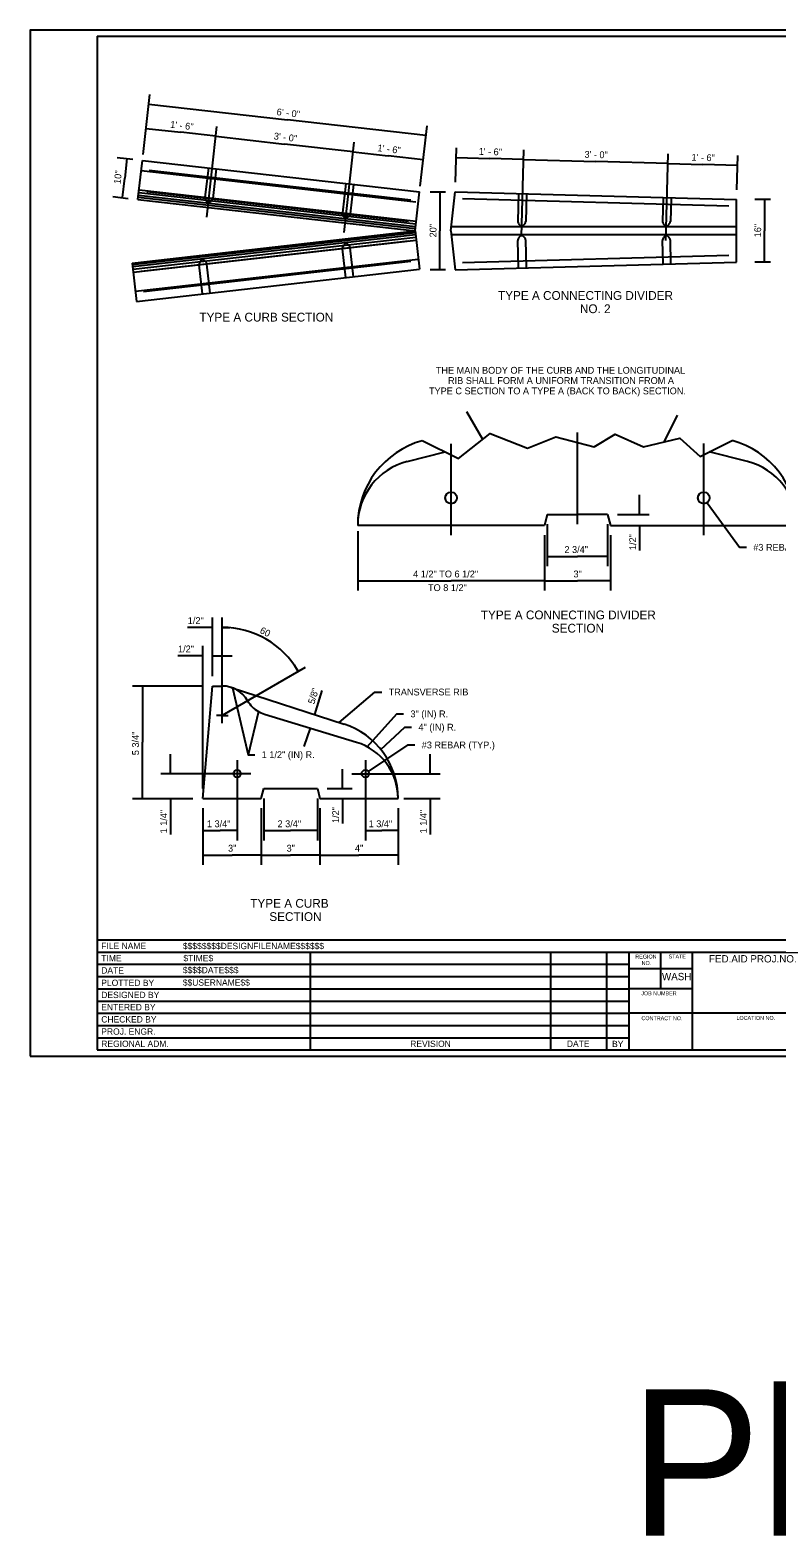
# Model space of a CAD drawing. Extents: x 99988 to 100172, y 99995 to 100047.
# Drawn here: x 99999.31 to 100006.96, y 99995.01 to 100010.44 of the extents above; entities that cross this region are included whole.
import ezdxf

# ---------------------------------------------------------------- set-up
doc = ezdxf.new("R2010")
doc.units = 0
for name, color, linetype in [('Level 1', 7, 'Continuous'), ('Level 15', 7, 'Continuous'), ('Level 2', 7, 'Continuous'), ('Level 20', 7, 'Continuous'), ('Level 27', 7, 'Continuous'), ('SH_GI_PlotLimits', 7, 'Continuous'), ('SH_GI_SheetBorder', 7, 'Continuous'), ('SH_GI_SheetLocationText', 7, 'Continuous'), ('SH_GI_SheetTextInCells', 7, 'Continuous'), ('SH_GI_TitleBlockText', 7, 'Continuous'), ('SH_RS_ConstructionNoteFlag', 7, 'Continuous'), ('SH_RS_DimensionLines', 7, 'Continuous')]:
    doc.layers.add(name, color=color, linetype=linetype)

msp = doc.modelspace()

# ---------------------------------------------------------------- linework, layer by layer
at = {"layer": 'Level 1'}
for centre, radius in [((100003.624, 100005.65), 0.06), ((100006.211, 100005.65), 0.06), ((100001.433, 100002.827), 0.0379), ((100002.746, 100002.827), 0.0379)]:
    msp.add_circle(centre, radius, dxfattribs=at)
at = {"layer": 'Level 15'}
for p, q in [((100000.469, 100009.164), (100000.539, 100009.78)), ((100000.528, 100009.681), (100001.947, 100009.52)), ((100000.5, 100009.432), (100000.857, 100009.392)), ((100001.214, 100009.351), (100000.857, 100009.392)), ((100001.121, 100008.524), (100001.226, 100009.451)), ((100003.366, 100009.359), (100001.947, 100009.52)), ((100003.308, 100008.842), (100003.377, 100009.458)), ((100001.214, 100009.351), (100001.918, 100009.272)), ((100002.621, 100009.192), (100001.918, 100009.272)), ((100002.527, 100008.365), (100002.632, 100009.291)), ((100003.67, 100008.883), (100003.68, 100009.233)), ((100004.344, 100008.324), (100004.368, 100009.214)), ((100000.204, 100009.134), (100000.363, 100009.116)), ((100000.303, 100009.123), (100000.281, 100008.923)), ((100002.621, 100009.192), (100002.978, 100009.151)), ((100003.336, 100009.111), (100002.978, 100009.151)), ((100003.677, 100009.133), (100004.021, 100009.124)), ((100004.366, 100009.114), (100004.021, 100009.124)), ((100004.366, 100009.114), (100005.105, 100009.094)), ((100005.845, 100009.073), (100005.105, 100009.094)), ((100005.823, 100008.283), (100005.848, 100009.173)), ((100005.845, 100009.073), (100006.201, 100009.063)), ((100006.557, 100009.053), (100006.201, 100009.063)), ((100006.55, 100008.803), (100006.56, 100009.153)), ((100000.258, 100008.723), (100000.281, 100008.923)), ((100003.409, 100008.783), (100003.566, 100008.783)), ((100003.509, 100008.783), (100003.509, 100008.383)), ((100000.159, 100008.734), (100000.318, 100008.716)), ((100006.894, 100008.704), (100006.734, 100008.704)), ((100006.834, 100008.704), (100006.834, 100008.384)), ((100003.509, 100007.984), (100003.509, 100008.383)), ((100006.834, 100008.064), (100006.834, 100008.384)), ((100003.566, 100007.984), (100003.409, 100007.984)), ((100006.894, 100008.064), (100006.734, 100008.064)), ((100003.948, 100006.249), (100003.785, 100006.53)), ((100005.805, 100006.222), (100005.942, 100006.498)), ((100004.917, 100005.381), (100004.917, 100006.32)), ((100003.624, 100005.268), (100003.624, 100006.202)), ((100006.211, 100005.268), (100006.211, 100006.205)), ((100004.608, 100005.381), (100004.608, 100004.951)), ((100005.227, 100005.381), (100005.227, 100004.951)), ((100005.327, 100005.481), (100005.653, 100005.481)), ((100002.667, 100005.308), (100002.667, 100004.701)), ((100004.58, 100005.268), (100004.58, 100004.701)), ((100005.255, 100005.268), (100005.255, 100004.701)), ((100004.608, 100005.051), (100004.917, 100005.051)), ((100005.227, 100005.051), (100004.917, 100005.051)), ((100002.667, 100004.801), (100003.624, 100004.801)), ((100004.58, 100004.801), (100003.624, 100004.801)), ((100004.58, 100004.801), (100004.917, 100004.801)), ((100005.255, 100004.801), (100004.917, 100004.801)), ((100001.18, 100003.824), (100001.18, 100004.424)), ((100001.28, 100003.344), (100001.28, 100004.424)), ((100001.08, 100002.674), (100001.08, 100004.134)), ((100002.129, 100003.914), (100001.28, 100003.424)), ((100001.08, 100003.724), (100000.362, 100003.724)), ((100000.462, 100003.724), (100000.462, 100003.149)), ((100001.28, 100003.424), (100001.22, 100003.424)), ((100001.28, 100003.424), (100001.34, 100003.424)), ((100000.462, 100002.574), (100000.462, 100003.149)), ((100000.75, 100002.827), (100000.75, 100003.027)), ((100003.41, 100002.827), (100003.41, 100003.027)), ((100002.355, 100002.674), (100002.611, 100002.674)), ((100000.362, 100002.574), (100000.98, 100002.574)), ((100001.08, 100002.474), (100001.08, 100001.894)), ((100001.68, 100002.474), (100001.68, 100001.894)), ((100001.705, 100002.574), (100001.705, 100002.144)), ((100002.255, 100002.574), (100002.255, 100002.144)), ((100002.28, 100002.474), (100002.28, 100001.894)), ((100003.08, 100002.474), (100003.08, 100001.894)), ((100003.14, 100002.574), (100003.51, 100002.574)), ((100001.08, 100002.244), (100001.257, 100002.244)), ((100001.433, 100002.244), (100001.257, 100002.244)), ((100001.705, 100002.244), (100001.98, 100002.244)), ((100002.255, 100002.244), (100001.98, 100002.244)), ((100002.746, 100002.244), (100002.913, 100002.244)), ((100003.08, 100002.244), (100002.913, 100002.244)), ((100001.08, 100001.994), (100001.38, 100001.994)), ((100001.68, 100001.994), (100001.38, 100001.994)), ((100001.68, 100001.994), (100001.98, 100001.994)), ((100002.28, 100001.994), (100001.98, 100001.994)), ((100002.28, 100001.994), (100002.68, 100001.994)), ((100003.08, 100001.994), (100002.68, 100001.994))]:
    msp.add_line(p, q, dxfattribs=at)
for points in [[(100006.246, 100005.601), (100006.578, 100005.144), (100006.648, 100005.144)], [(100001.28, 100004.324), (100001.355, 100004.321)], [(100002.059, 100003.874), (100002.019, 100003.937)], [(100001.386, 100003.705), (100001.544, 100003.021)], [(100002.476, 100003.352), (100002.844, 100003.663), (100002.914, 100003.663)], [(100001.65, 100003.464), (100001.544, 100003.021), (100001.614, 100003.021)], [(100002.763, 100003.103), (100003.067, 100003.439), (100003.137, 100003.439)], [(100002.903, 100003.076), (100003.149, 100003.303), (100003.219, 100003.303)], [(100002.777, 100002.848), (100003.183, 100003.121), (100003.253, 100003.121)]]:
    msp.add_lwpolyline(points, dxfattribs=at)
msp.add_arc((100001.28, 100003.424), 0.9, 30.0003, 90, dxfattribs=at)
at = {"layer": 'Level 2'}
for p, q in [((100000.417, 100008.705), (100000.462, 100009.105)), ((100000.462, 100009.105), (100003.301, 100008.783)), ((100000.531, 100009.004), (100003.211, 100008.7)), ((100001.138, 100009.028), (100001.103, 100008.724)), ((100001.218, 100009.019), (100001.183, 100008.715)), ((100000.507, 100008.787), (100003.186, 100008.484)), ((100002.544, 100008.868), (100002.51, 100008.566)), ((100002.625, 100008.859), (100002.59, 100008.556)), ((100003.255, 100008.383), (100003.301, 100008.783)), ((100003.622, 100008.384), (100003.667, 100008.784)), ((100003.667, 100008.784), (100006.547, 100008.704)), ((100004.315, 100008.767), (100004.308, 100008.482)), ((100004.396, 100008.762), (100004.388, 100008.48)), ((100000.417, 100008.705), (100003.255, 100008.383)), ((100003.257, 100008.404), (100000.419, 100008.724)), ((100001.136, 100008.663), (100001.111, 100008.695)), ((100001.136, 100008.663), (100001.168, 100008.688)), ((100006.467, 100008.635), (100003.739, 100008.711)), ((100005.795, 100008.726), (100005.788, 100008.482)), ((100005.876, 100008.721), (100005.869, 100008.48)), ((100006.547, 100008.064), (100006.547, 100008.704)), ((100002.543, 100008.504), (100002.518, 100008.536)), ((100002.543, 100008.504), (100002.575, 100008.53)), ((100004.346, 100008.424), (100004.318, 100008.453)), ((100004.346, 100008.424), (100004.376, 100008.452)), ((100005.827, 100008.424), (100005.799, 100008.453)), ((100005.827, 100008.424), (100005.857, 100008.452)), ((100000.359, 100008.054), (100003.255, 100008.383)), ((100003.258, 100008.362), (100000.361, 100008.035)), ((100003.255, 100008.383), (100003.3, 100007.99)), ((100003.622, 100008.384), (100003.667, 100007.984)), ((100004.346, 100008.343), (100004.318, 100008.314)), ((100004.346, 100008.343), (100004.376, 100008.315)), ((100005.827, 100008.343), (100005.799, 100008.314)), ((100005.827, 100008.343), (100005.856, 100008.315)), ((100000.449, 100007.971), (100003.186, 100008.282)), ((100002.544, 100007.904), (100002.51, 100008.2)), ((100002.544, 100008.261), (100002.519, 100008.229)), ((100002.544, 100008.261), (100002.575, 100008.236)), ((100002.624, 100007.913), (100002.59, 100008.209)), ((100004.315, 100008), (100004.307, 100008.285)), ((100004.396, 100008.005), (100004.388, 100008.287)), ((100005.795, 100008.041), (100005.788, 100008.285)), ((100005.875, 100008.046), (100005.869, 100008.287)), ((100000.359, 100008.054), (100000.403, 100007.661)), ((100000.403, 100007.661), (100003.3, 100007.99)), ((100000.472, 100007.762), (100003.21, 100008.073)), ((100001.076, 100007.738), (100001.042, 100008.034)), ((100001.075, 100008.095), (100001.05, 100008.064)), ((100001.075, 100008.095), (100001.107, 100008.07)), ((100001.156, 100007.747), (100001.122, 100008.043)), ((100003.667, 100007.984), (100006.547, 100008.064)), ((100006.467, 100008.131), (100003.739, 100008.055)), ((100003.175, 100006.022), (100003.564, 100006.121)), ((100003.175, 100006.022), (100003.175, 100006.022)), ((100006.66, 100006.022), (100006.268, 100006.121)), ((100006.66, 100006.022), (100006.66, 100006.022)), ((100004.58, 100005.368), (100002.667, 100005.368)), ((100004.608, 100005.481), (100004.58, 100005.368)), ((100004.608, 100005.481), (100004.917, 100005.481)), ((100005.227, 100005.481), (100004.917, 100005.481)), ((100005.227, 100005.481), (100005.255, 100005.368)), ((100005.255, 100005.368), (100007.167, 100005.368)), ((100001.08, 100002.574), (100001.18, 100003.724)), ((100001.18, 100003.724), (100001.28, 100003.724)), ((100001.372, 100003.71), (100002.527, 100003.335)), ((100001.711, 100003.437), (100002.656, 100003.148)), ((100001.433, 100002.964), (100001.433, 100002.144)), ((100002.746, 100002.964), (100002.746, 100002.144)), ((100001.571, 100002.827), (100000.65, 100002.827)), ((100002.608, 100002.827), (100003.51, 100002.827)), ((100001.68, 100002.574), (100001.705, 100002.674)), ((100001.705, 100002.674), (100002.255, 100002.674)), ((100002.255, 100002.674), (100002.28, 100002.574)), ((100001.08, 100002.574), (100001.68, 100002.574)), ((100002.28, 100002.574), (100003.08, 100002.574))]:
    msp.add_line(p, q, dxfattribs=at)
msp.add_lwpolyline([(100003.328, 100006.236), (100003.7, 100006.054), (100004.025, 100006.31), (100004.405, 100006.158), (100004.695, 100006.275), (100005.089, 100006.171), (100005.303, 100006.303), (100005.593, 100006.171), (100005.967, 100006.261), (100006.174, 100006.075), (100006.503, 100006.237)], dxfattribs=at)
for centre, radius, start, end in [((100001.142, 100008.72), 0.04, 173.435, 218.435), ((100001.143, 100008.72), 0.04, 308.435, 353.435), ((100002.549, 100008.561), 0.04, 173.435, 218.435), ((100002.55, 100008.561), 0.04, 308.435, 353.435), ((100004.348, 100008.481), 0.04, 178.4171, 223.4171), ((100004.348, 100008.481), 0.04, 313.4171, 358.4171), ((100005.828, 100008.481), 0.04, 178.4298, 223.4298), ((100005.829, 100008.481), 0.04, 313.4298, 358.4298), ((100004.347, 100008.286), 0.04, 136.5372, 181.5372), ((100004.348, 100008.286), 0.04, 1.5372, 46.5372), ((100005.828, 100008.286), 0.04, 136.5467, 181.5467), ((100005.829, 100008.286), 0.04, 1.5467, 46.5467), ((100002.55, 100008.204), 0.04, 141.5636, 186.5636), ((100002.551, 100008.205), 0.04, 6.5636, 51.5636), ((100001.082, 100008.039), 0.04, 141.5636, 186.5636), ((100001.082, 100008.039), 0.04, 6.5636, 51.5636), ((100003.567, 100005.368), 0.9, 105.4337, 180), ((100006.267, 100005.368), 0.9, 0, 74.8377), ((100003.342, 100005.368), 0.675, 104.338, 180), ((100006.492, 100005.368), 0.675, 0, 75.662), ((100001.28, 100003.424), 0.3, 30, 90), ((100001.799, 100003.724), 0.3, 210, 240.2155), ((100001.799, 100003.724), 0.3, 240.2155, 252.9521), ((100002.28, 100002.574), 0.8, 0, 72.0292), ((100002.48, 100002.574), 0.6, 0, 72.9521)]:
    msp.add_arc(centre, radius, start, end, dxfattribs=at)
at = {"layer": 'Level 27'}
for p, q in [((100000.451, 100009), (100003.263, 100008.681)), ((100003.262, 100008.452), (100000.425, 100008.772)), ((100003.265, 100008.48), (100000.428, 100008.801)), ((100003.259, 100008.424), (100000.421, 100008.744)), ((100003.26, 100008.342), (100000.363, 100008.015)), ((100003.263, 100008.314), (100000.366, 100007.987)), ((100006.547, 100008.424), (100003.626, 100008.424)), ((100006.547, 100008.343), (100003.626, 100008.343)), ((100003.266, 100008.285), (100000.37, 100007.958)), ((100000.391, 100007.766), (100003.288, 100008.094))]:
    msp.add_line(p, q, dxfattribs=at)
at = {"layer": 'SH_GI_PlotLimits'}
msp.add_lwpolyline([(99999.312, 99999.937), (100015.812, 99999.937), (100015.812, 100010.437), (99999.312, 100010.437)], close=True, dxfattribs=at)
at = {"layer": 'SH_GI_SheetBorder'}
for p, q in [((100000, 100010.375), (100000, 100000)), ((100000, 100010.375), (100015.75, 100010.375)), ((100000, 100001.126), (100015.75, 100001.126)), ((100000, 100001.001), (100007.457, 100001.001)), ((100002.179, 100001.001), (100002.179, 100000)), ((100004.641, 100001.001), (100004.641, 100000)), ((100005.216, 100001.001), (100005.216, 100000)), ((100005.445, 100001.001), (100005.445, 100000)), ((100005.772, 100000.625), (100005.772, 100001.001)), ((100006.096, 100000), (100006.096, 100001.001)), ((100000, 100000.876), (100002.182, 100000.876)), ((100000, 100000.751), (100002.182, 100000.751)), ((100002.182, 100000.876), (100005.447, 100000.876)), ((100002.182, 100000.751), (100005.447, 100000.751)), ((100006.096, 100000.831), (100005.447, 100000.831)), ((100000, 100000.625), (100005.447, 100000.625)), ((100006.096, 100000.625), (100005.447, 100000.625)), ((100000, 100000.5), (100005.447, 100000.5)), ((100000, 100000.375), (100005.447, 100000.375)), ((100007.457, 100000.375), (100005.447, 100000.375)), ((100000, 100000.25), (100005.447, 100000.25)), ((100000, 100000.125), (100005.447, 100000.125)), ((100000, 100000), (100015.75, 100000))]:
    msp.add_line(p, q, dxfattribs=at)
at = {"layer": 'SH_RS_DimensionLines'}
for p, q in [((100005.553, 100005.481), (100005.553, 100005.681)), ((100005.553, 100005.368), (100005.553, 100005.112)), ((100001.18, 100004.324), (100000.924, 100004.324)), ((100001.08, 100004.034), (100000.824, 100004.034)), ((100001.18, 100004.034), (100001.38, 100004.034)), ((100002.227, 100003.432), (100002.304, 100003.677)), ((100002.227, 100003.432), (100002.287, 100003.623)), ((100002.181, 100003.293), (100002.117, 100003.104)), ((100002.511, 100002.674), (100002.511, 100002.874)), ((100000.75, 100002.574), (100000.75, 100002.206)), ((100002.511, 100002.574), (100002.511, 100002.318)), ((100003.41, 100002.574), (100003.41, 100002.206))]:
    msp.add_line(p, q, dxfattribs=at)

# ---------------------------------------------------------------- texts
at = {"layer": 'Level 20'}
for s, rotation, p in [('6\' - 0"', 353.5303, (100001.834, 100009.568)), ('1\' - 6"', 353.5303, (100000.744, 100009.44)), ('3\' - 0"', 353.5303, (100001.805, 100009.32)), ('1\' - 6"', 353.5303, (100002.866, 100009.199)), ('1\' - 6"', 358.4089, (100003.905, 100009.162)), ('3\' - 0"', 358.4089, (100004.989, 100009.132)), ('1\' - 6"', 358.4089, (100006.085, 100009.102)), ('10"', 83.5303, (100000.238, 100008.86)), ('20"', 90, (100003.474, 100008.316)), ('16"', 90, (100006.799, 100008.317)), ('THE MAIN BODY OF THE CURB AND THE LONGITUDINAL ', 360, (100003.467, 100006.921)), ('TYPE C SECTION TO A TYPE A (BACK TO BACK) SECTION.', 360, (100003.397, 100006.71)), ('RIB SHALL FORM A UNIFORM TRANSITION FROM A', 360, (100003.592, 100006.816)), ('#3 REBAR (TYP.)', 360, (100006.718, 100005.109)), ('60', 332.6326, (100001.658, 100004.271)), ('TRANSVERSE RIB', 360, (100002.984, 100003.628)), ('3" (IN) R.', 360, (100003.207, 100003.404)), ('5 3/4"', 90, (100000.427, 100003.016)), ('4" (IN) R.', 360, (100003.289, 100003.268)), ('1 1/2" (IN) R.', 360, (100001.684, 100002.986)), ('#3 REBAR (TYP.)', 360, (100003.323, 100003.086)), ('1 3/4"', 360, (100002.779, 100002.279)), ('3"', 360, (100001.339, 100002.029)), ('3"', 360, (100001.939, 100002.029))]:
    msp.add_text(s, height=0.07, rotation=rotation, dxfattribs=at).set_placement(p)
for s, height, p in [('TYPE A CONNECTING DIVIDER', 0.09, (100004.104, 100007.677)), ('TYPE A CURB SECTION', 0.09, (100001.046, 100007.455)), ('NO. 2', 0.09, (100004.943, 100007.541)), ('2 3/4"', 0.07, (100004.784, 100005.086)), ('4 1/2" TO 6 1/2"', 0.07, (100003.235, 100004.836)), ('3"', 0.07, (100004.877, 100004.836)), ('TO 8 1/2"', 0.07, (100003.387, 100004.696)), ('TYPE A CONNECTING DIVIDER', 0.09, (100003.928, 100004.407)), ('SECTION', 0.09, (100004.655, 100004.271)), ('1 3/4"', 0.07, (100001.123, 100002.279)), ('2 3/4"', 0.07, (100001.846, 100002.279)), ('4"', 0.07, (100002.639, 100002.029)), ('TYPE A CURB', 0.09, (100001.567, 100001.455)), ('SECTION', 0.09, (100001.762, 100001.319))]:
    msp.add_text(s, height=height, dxfattribs=at).set_placement(p)
at = {"layer": 'SH_GI_SheetLocationText'}
msp.add_text('Plot 1', height=1.5, dxfattribs=at).set_placement((100005.455, 99995.027))
at = {"layer": 'SH_GI_SheetTextInCells'}
for s, height, p in [('FILE NAME', 0.0651, (100000.041, 100001.031)), ('TIME', 0.0651, (100000.041, 100000.906)), ('REGION', 0.04, (100005.51, 100000.935)), ('NO.', 0.04, (100005.575, 100000.869)), ('STATE', 0.04, (100005.851, 100000.936)), ('FED.AID PROJ.NO.', 0.07506, (100006.265, 100000.895)), ('DATE', 0.0651, (100000.041, 100000.781)), ('WASH', 0.0751, (100005.783, 100000.713)), ('PLOTTED BY', 0.0651, (100000.041, 100000.654)), ('DESIGNED BY', 0.06505, (100000.041, 100000.53)), ('JOB NUMBER', 0.04, (100005.571, 100000.559)), ('ENTERED BY', 0.0651, (100000.041, 100000.405)), ('CHECKED BY', 0.0651, (100000.041, 100000.28)), ('CONTRACT NO.', 0.04003, (100005.573, 100000.304)), ('LOCATION NO.', 0.04003, (100006.546, 100000.307)), ('PROJ. ENGR.', 0.06505, (100000.041, 100000.155)), ('REGIONAL ADM.', 0.06505, (100000.041, 100000.03)), ('REVISION', 0.0651, (100003.205, 100000.03)), ('DATE', 0.0651, (100004.809, 100000.03)), ('BY', 0.0651, (100005.272, 100000.028))]:
    msp.add_text(s, height=height, dxfattribs=at).set_placement(p)
at = {"layer": 'SH_GI_TitleBlockText'}
for s, height, p in [('$$$$$$$$DESIGNFILENAME$$$$$$', 0.06505, (100000.877, 100001.031)), ('$TIME$', 0.0651, (100000.882, 100000.906)), ('$$$$DATE$$$', 0.06505, (100000.876, 100000.784)), ('$$USERNAME$$', 0.06505, (100000.876, 100000.657))]:
    msp.add_text(s, height=height, dxfattribs=at).set_placement(p)
at = {"layer": 'SH_RS_ConstructionNoteFlag'}
for s, rotation, p in [('1/2"', 90, (100005.518, 100005.116)), ('1/2"', 360, (100000.927, 100004.359)), ('1/2"', 360, (100000.827, 100004.069)), ('5/8"', 72.608, (100002.222, 100003.533)), ('1 1/4"', 90, (100000.715, 100002.216)), ('1/2"', 90, (100002.476, 100002.322)), ('1 1/4"', 90, (100003.375, 100002.216))]:
    msp.add_text(s, height=0.07, rotation=rotation, dxfattribs=at).set_placement(p)

doc.saveas('drawing.dxf')
